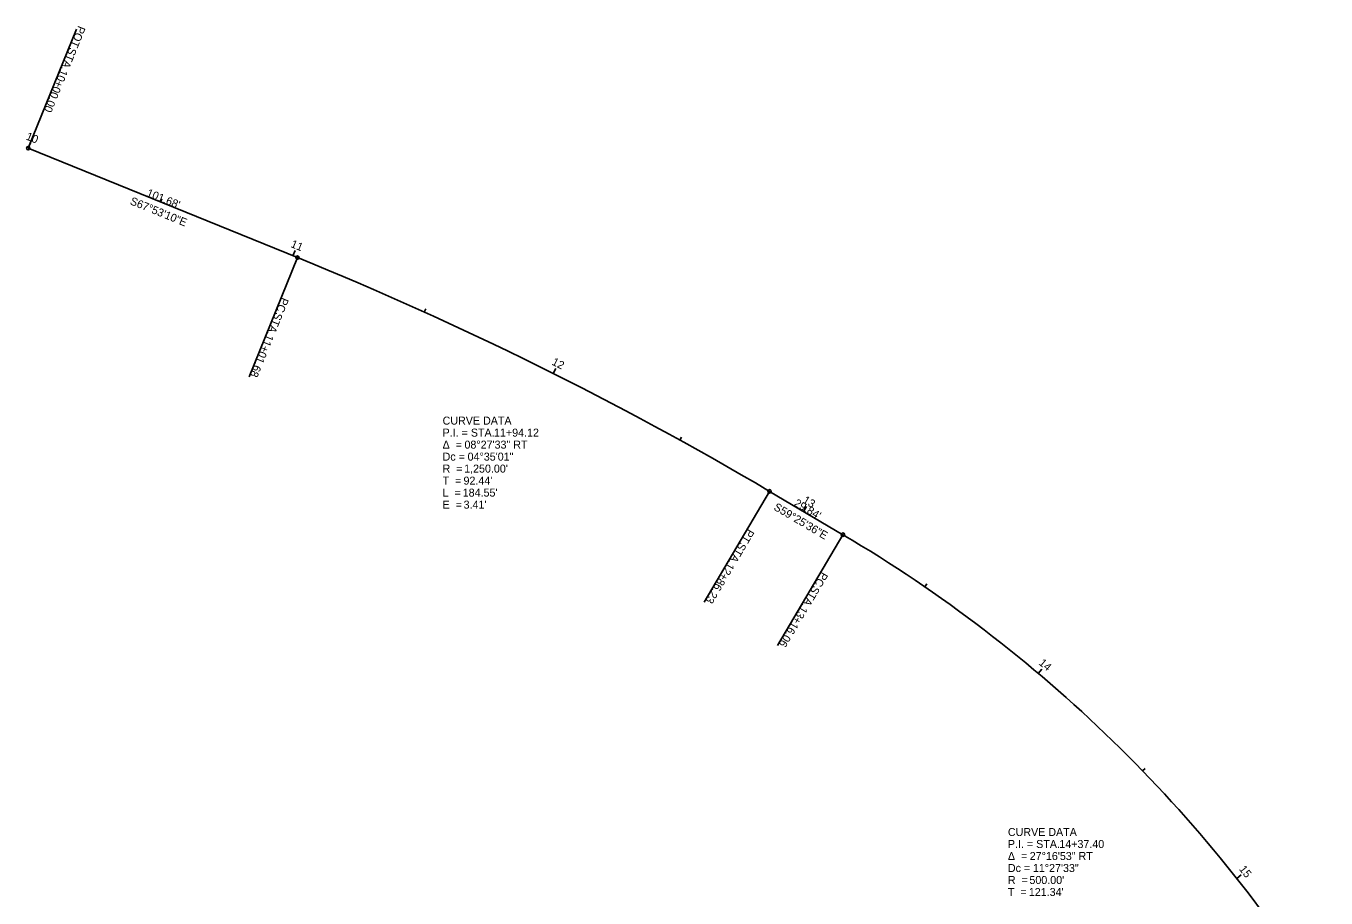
# Model space of a CAD drawing. Extents: x 1927094 to 1928117, y 199395 to 200287.
# Drawn here: x 1927093.9 to 1927548.9, y 199981.6 to 200286.7 of the extents above; entities that cross this region are included whole.
import ezdxf

# ---------------------------------------------------------------- set-up
doc = ezdxf.new("R2010")
doc.units = 0
for name, color, linetype in [('GE_X_Alignment', 7, 'Continuous'), ('GE_X_Alignment_100_Bearings', 7, 'Continuous'), ('GE_X_Alignment_100_Cardinal_Points', 7, 'Continuous'), ('GE_X_Alignment_100_Curve_Data', 7, 'Continuous'), ('GE_X_Alignment_100_Distances', 7, 'Continuous'), ('GE_X_Alignment_100_Stations', 7, 'Continuous')]:
    doc.layers.add(name, color=color, linetype=linetype)

msp = doc.modelspace()

# ---------------------------------------------------------------- linework, layer by layer
at = {"layer": 'GE_X_Alignment'}
for p, q in [((1927094.72, 200243.98), (1927188.91, 200205.7)), ((1927354.15, 200123.88), (1927379.84, 200108.71))]:
    msp.add_line(p, q, dxfattribs=at)
for centre, radius, start, end in [((1926718.35, 199047.66), 1250, 59.42679, 67.88606), ((1927125.52, 199678.22), 500, 32.1455, 59.4268)]:
    msp.add_arc(centre, radius, start, end, dxfattribs=at)
at = {"layer": 'GE_X_Alignment_100_Cardinal_Points'}
for p, q in [((1927094.72, 200243.98), (1927111.66, 200285.67)), ((1927188.91, 200205.7), (1927171.97, 200164.01)), ((1927354.15, 200123.88), (1927331.26, 200085.14)), ((1927379.84, 200108.71), (1927356.95, 200069.96))]:
    msp.add_line(p, q, dxfattribs=at)
for centre in [(1927094.72, 200243.98), (1927188.91, 200205.7), (1927354.15, 200123.88), (1927379.84, 200108.71)]:
    msp.add_circle(centre, 0.6, dxfattribs=at)
at = {"layer": 'GE_X_Alignment_100_Stations'}
for p, q in [((1927094.72, 200243.98), (1927095.47, 200245.83)), ((1927141.04, 200225.16), (1927141.49, 200226.27)), ((1927187.36, 200206.33), (1927188.11, 200208.19)), ((1927233.32, 200186.65), (1927233.81, 200187.74)), ((1927278.46, 200165.15), (1927279.35, 200166.93)), ((1927322.7, 200141.85), (1927323.28, 200142.9)), ((1927366.01, 200116.88), (1927367.02, 200118.6)), ((1927408.45, 200090.47), (1927409.13, 200091.46)), ((1927448.19, 200060.16), (1927449.48, 200061.69)), ((1927484.71, 200026.04), (1927485.57, 200026.87)), ((1927517.64, 199988.44), (1927519.21, 199989.68))]:
    msp.add_line(p, q, dxfattribs=at)

# ---------------------------------------------------------------- texts
at = {"layer": 'GE_X_Alignment_100_Bearings'}
for s, rotation, p in [('S67°53\'10"E', 337.8861, (1927130.09, 200224.43)), ('S59°25\'36"E', 329.4268, (1927355.33, 200117.61))]:
    msp.add_text(s, height=2.8, rotation=rotation, dxfattribs=at).set_placement(p)
at = {"layer": 'GE_X_Alignment_100_Cardinal_Points'}
for s, rotation, p in [('POT', 247.8861, (1927112.25, 200287.03)), (' STA. ', 247.8861, (1927109.57, 200280.42)), ('10+00.00', 247.8861, (1927106.06, 200271.79)), ('PC', 247.8861, (1927183.38, 200191.98)), (' STA. ', 247.8861, (1927181.64, 200187.72)), ('11+01.68', 247.8861, (1927178.13, 200179.08)), ('PT', 239.4268, (1927346.56, 200110.97)), (' STA. ', 239.4268, (1927344.35, 200107.22)), ('12+86.23', 239.4268, (1927339.61, 200099.2)), ('PC', 239.4268, (1927372.35, 200095.95)), (' STA. ', 239.4268, (1927370.01, 200091.99)), ('13+16.06', 239.4268, (1927365.26, 200083.96))]:
    msp.add_text(s, height=2.8, rotation=rotation, dxfattribs=at).set_placement(p)
at = {"layer": 'GE_X_Alignment_100_Curve_Data'}
for s, p in [('CURVE DATA', (1927239.72, 200147.24)), ('P.I. = STA. ', (1927239.72, 200143.04)), ('11+94.12', (1927257.71, 200143.04)), ('Δ  = ', (1927239.72, 200138.84)), ('08°27\'33" RT', (1927247.37, 200138.84)), ('Dc = ', (1927239.72, 200134.64)), ('04°35\'01"', (1927248.47, 200134.64)), ('R  = ', (1927239.72, 200130.44)), ("1,250.00'", (1927247.26, 200130.44)), ('T  = ', (1927239.72, 200126.24)), ("92.44'", (1927247.04, 200126.24)), ('L  = ', (1927239.72, 200122.04)), ("184.55'", (1927246.76, 200122.04)), ('E  = ', (1927239.72, 200117.84)), ("3.41'", (1927247.07, 200117.84)), ('CURVE DATA', (1927437.55, 200003.26)), ('P.I. = STA. ', (1927437.55, 199999.06)), ('14+37.40', (1927455.54, 199999.06)), ('Δ  = ', (1927437.55, 199994.86)), ('27°16\'53" RT', (1927445.19, 199994.86)), ('Dc = ', (1927437.55, 199990.66)), ('11°27\'33"', (1927446.29, 199990.66)), ('R  = ', (1927437.55, 199986.46)), ("500.00'", (1927445.08, 199986.46)), ('T  = ', (1927437.55, 199982.26)), ("121.34'", (1927444.87, 199982.26))]:
    msp.add_text(s, height=2.8, dxfattribs=at).set_placement(p)
at = {"layer": 'GE_X_Alignment_100_Distances'}
for s, rotation, p in [("101.68'", 337.8861, (1927135.87, 200227.3)), ("29.84'", 329.4268, (1927362.43, 200119.03))]:
    msp.add_text(s, height=2.8, rotation=rotation, dxfattribs=at).set_placement(p)
at = {"layer": 'GE_X_Alignment_100_Stations'}
for s, rotation, p in [('10', 337.8861, (1927093.67, 200247.1)), ('11', 337.8861, (1927186.35, 200209.44)), ('12', 333.3792, (1927277.7, 200168.32)), ('13', 329.4268, (1927365.49, 200120.09)), ('14', 319.8085, (1927448.15, 200063.47)), ('15', 308.3493, (1927518.3, 199991.63))]:
    msp.add_text(s, height=2.8, rotation=rotation, dxfattribs=at).set_placement(p)

doc.saveas('drawing.dxf')
